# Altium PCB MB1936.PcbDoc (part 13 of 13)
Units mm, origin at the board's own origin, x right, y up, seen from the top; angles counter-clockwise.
Board outline 172 x 137 mm, 6 copper layers (Top Layer, Signal Layer 1, Signal Layer 2, Signal Layer 3, Signal Layer 4, Bottom Layer), stack 1.549 mm thick; 859 components, 672 nets, 3477 pads, 2222 vias.
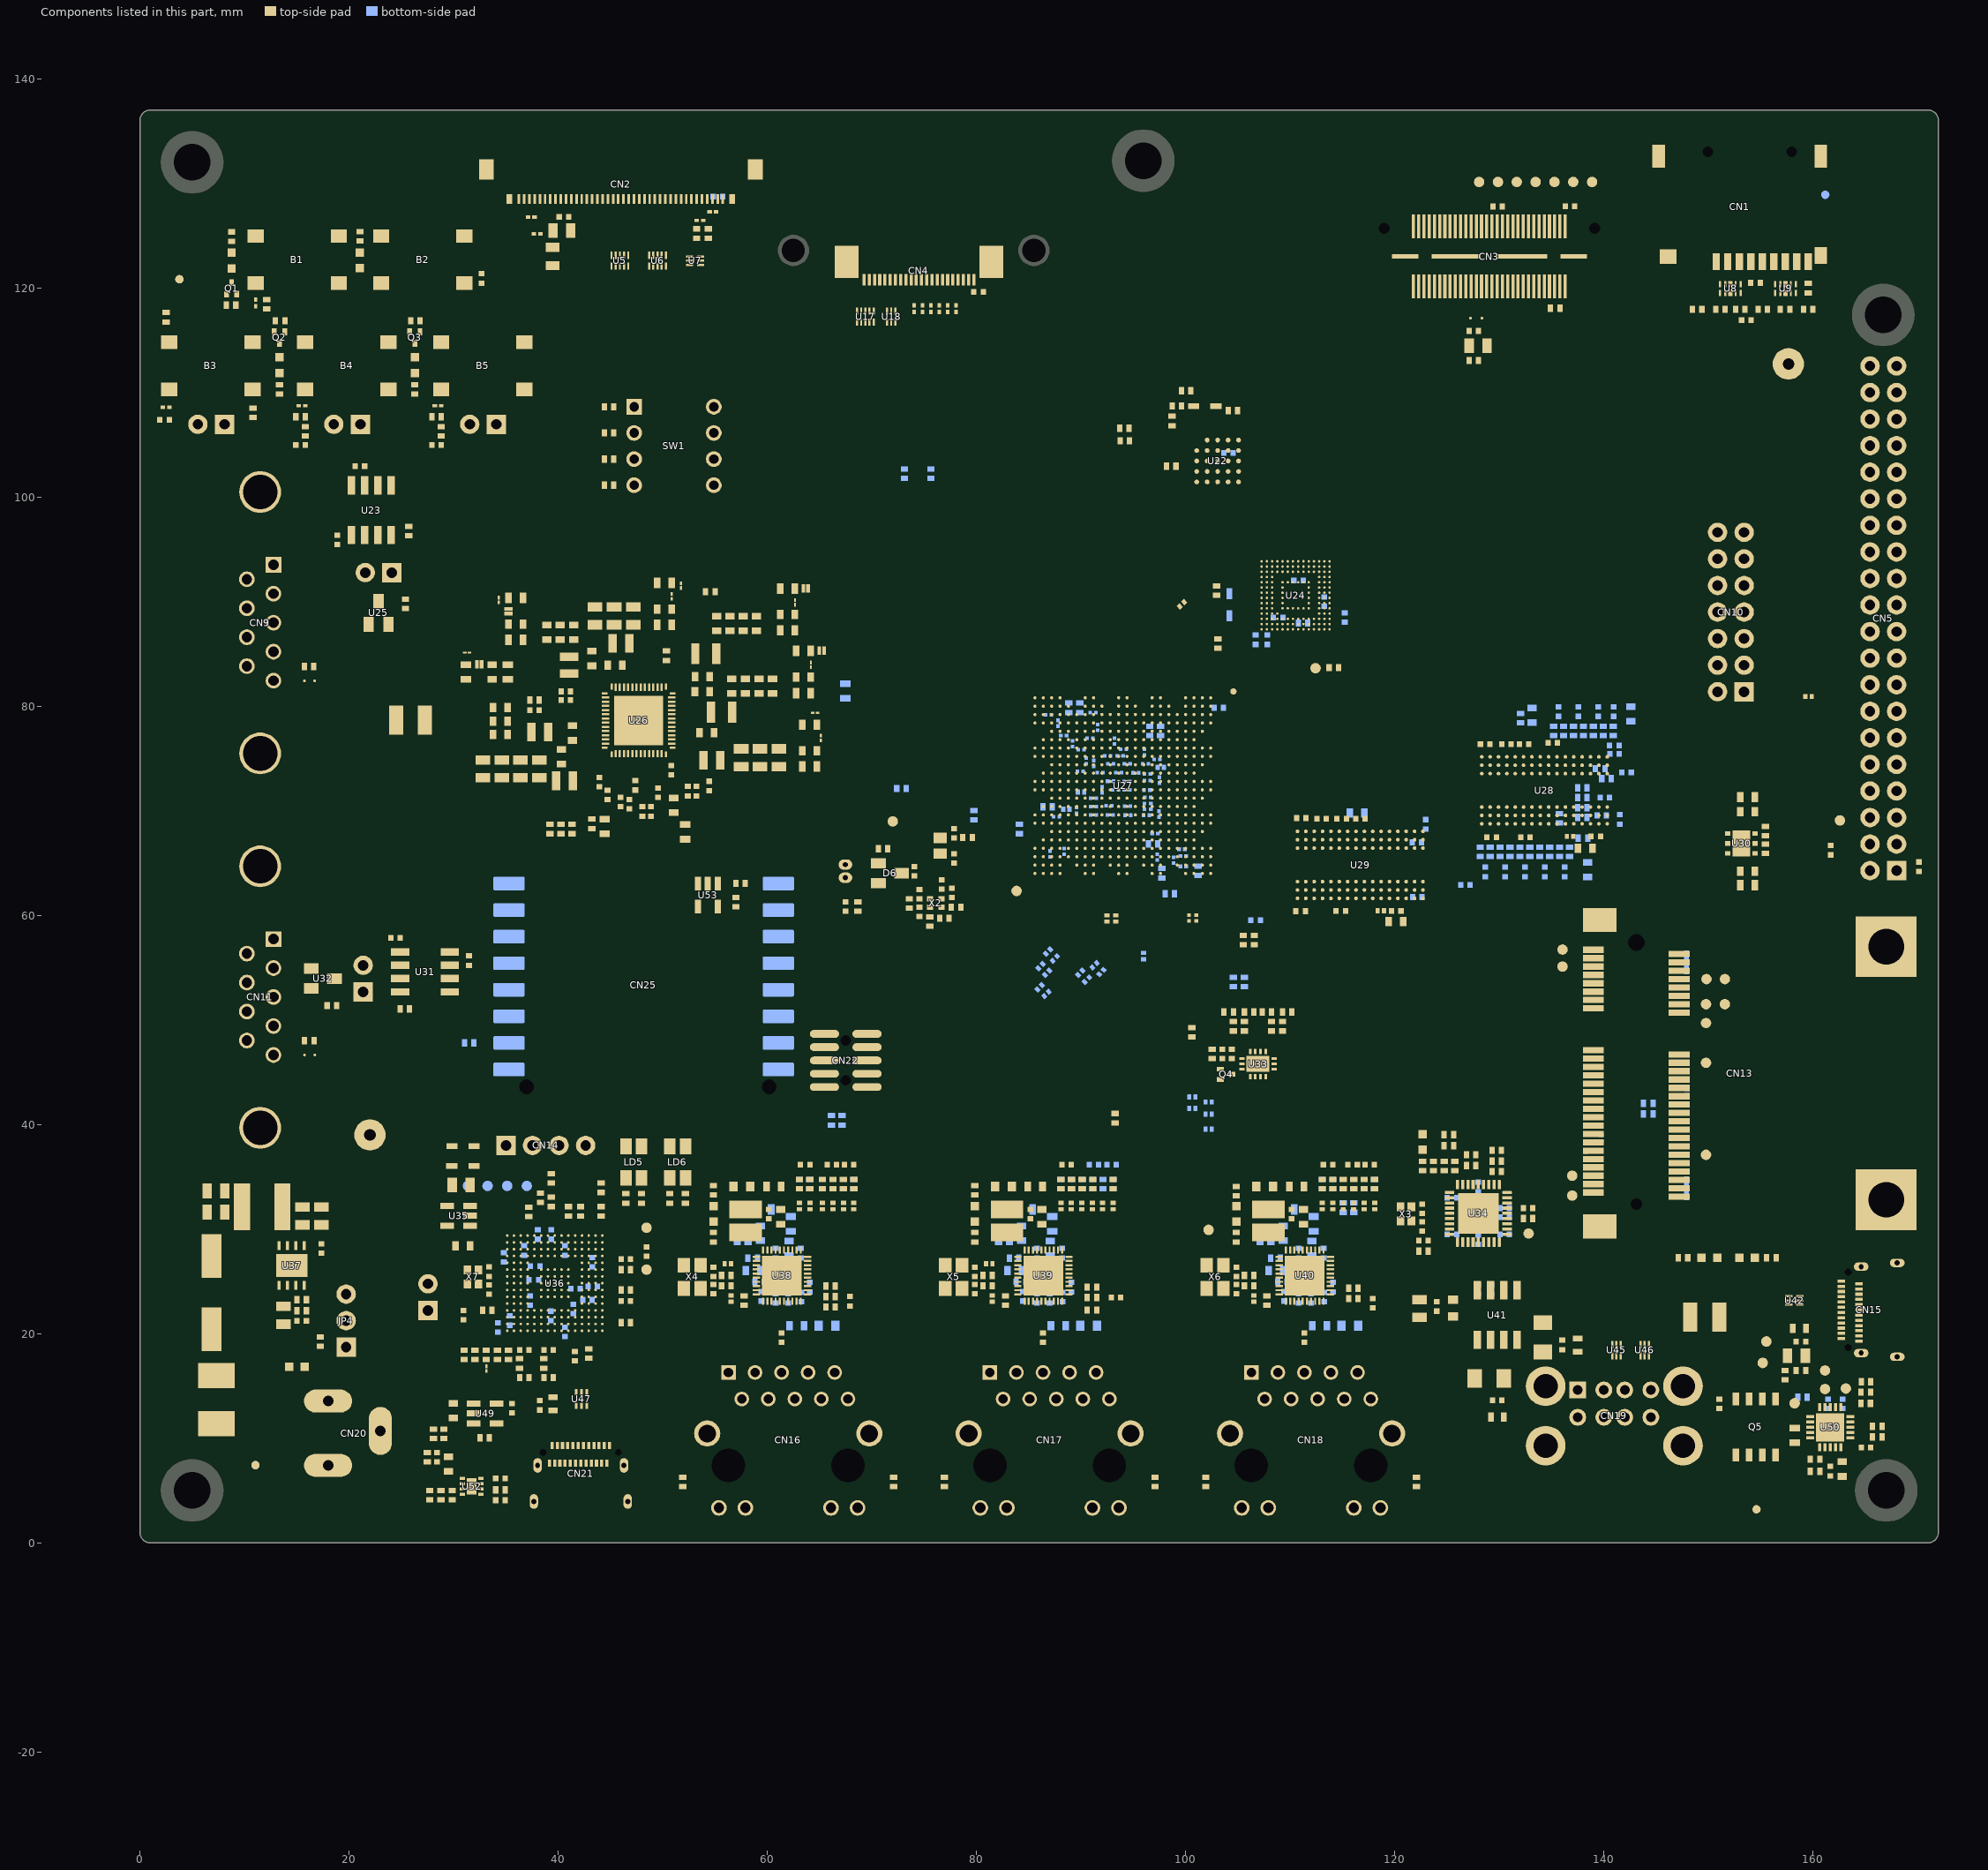
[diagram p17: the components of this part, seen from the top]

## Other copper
Top Layer:
  region net I_SENS_VDDGPU_N: 64.475,84 63.835,84 63.835,82.673 64.475,82.673
  rectangle net VDDGPU: 63.835,83.975 64.475,85.277
  region net I_SENS_VDDCORE_N: 62.95,89.95 62.31,89.95 62.31,88.973 62.95,88.973
  rectangle net VDDCORE: 62.31,89.924 62.95,90.875
  rectangle net VDDGPU: 64.4,84.9 64.95,85.7
  rectangle net VDDCORE: 62.875,90.875 63.425,91.675
  rectangle net 5V_VIN: 38.5,120.925 40.45,122.55
  rectangle net 5V_VIN: 121.675,22.8 123.075,25.2
  rectangle net 5V_VIN: 150.765,7.775 154.32,12.225
  region net NetL2_1: 51.225,80.352 51.55,80.352 52.025,80.827 52.025,83.102 52.027,83.135 52.036,83.166 52.049,83.197 52.064,83.226 52.083,83.254 52.103,83.279 52.127,83.303 52.151,83.323 52.18,83.342 52.208,83.357 52.239,83.37 52.27,83.38 52.303,83.386 52.337,83.389 52.475,83.527 52.475,83.577 52.475,83.651 cw(c52.85,83.651) 52.85,84.026 52.85,86.027 51.62,86.027 ccw(c51.8,85.727) 51.45,85.727 51.45,82.152 51.47,82.149 51.597,82.096 51.709,81.984 51.77,81.837 51.77,81.677 51.725,81.569 51.725,81.018 51.705,80.921 51.65,80.838 51.47,80.658 51.314,80.502 51.225,80.502
  region net NetL1_1: 46.772,84.702 ccw(c46.469,84.71) 46.678,84.929 46.655,84.952 46.655,85.014 46.726,85.021 46.875,84.902
  region net GND: 51.425,78.827 51.35,78.752 51.272,78.752 cw(c51.272,78.625) 51.362,78.715 51.388,78.689 ccw(c51.478,78.779) 51.478,78.652 52.147,78.652 cw(c52.147,78.525) 52.237,78.615 52.3,78.552 52.429,78.681 cw(c52.48,78.63) 52.48,78.702
  region net 5V_VIN: 53.525,82.152 53.525,83.227 52.352,83.227 ccw(c52.352,83.055) 52.18,83.054 52.18,80.646 51.706,80.172 51.47,80.172 51.47,79.907 52.076,79.907 52.547,80.378 52.549,80.365 52.55,80.366 52.55,81.486 52.539,81.497 52.496,81.563 52.465,81.635 52.45,81.713 52.45,81.827 cw(c52.813,81.789) 52.775,82.152
  region net 5V_VIN: 44.43,83.351 44.331,83.252 43.975,83.252 cw(c43.975,83.602) 43.625,83.602 43.625,83.652 42.9,83.652 ccw(c42.9,83.577) 42.825,83.577 42.825,83.227 ccw(c43.027,83.224) 43.025,83.022 45.65,83.022 46.05,82.627 46.312,82.627 45.591,83.348 45.325,83.352
  region net GND: 44.1,82.512 44.007,82.512 ccw(c44.007,82.411) 43.935,82.482 43.655,82.202 ccw(c43.727,82.13) 43.625,82.13 43.625,81.802 44.125,81.802 cw(c44.523,81.809) 44.515,82.207 44.775,82.202 ccw(c44.775,82.25) 44.809,82.216 44.905,82.312
  pour cut-out: 29.525,11.23 29.525,9.62 29.505,9.6 29.1,9.6 28.805,9.305 28.805,7.521 27.074,7.521 26.975,7.62 26.975,8.975 27.62,9.62 27.62,11.23
  region net NetL4_1: 53.725,80.427 53.725,78.427 54.634,78.427 54.634,80.427
  region net NetL3_1: 41.775,81.802 40.588,82.989 41.688,82.989 41.775,82.902 45.38,82.902 45.62,82.662 43.99,82.662 43.968,82.66 43.948,82.656 43.92,82.647 43.901,82.64 43.875,82.626 43.858,82.615 43.835,82.596 43.541,82.301 43.522,82.279 43.511,82.262 43.502,82.246 43.49,82.217 43.486,82.205 43.481,82.189 43.477,82.169 43.476,82.154 43.474,82.14 43.474,81.802
  region net NetL3_1: 42.983,82.872 42.954,82.875 42.925,82.884 42.851,82.916 42.825,82.93 42.803,82.949 42.747,83.007 42.728,83.03 42.714,83.056 42.688,83.121 42.681,83.143 42.658,83.174 42.633,83.194 42.597,83.218 42.551,83.227 41.775,83.227 41.775,82.09
  region net NetL7_1: 42.075,73.177 41.775,72.877 41,72.877 41,73.777 42.075,74.847
  region net NetL1_1: 47.195,85.102 46.85,84.757 46.395,85.212 46.395,86.902 47.195,86.902
  region net NetL5_1: 38.625,78.775 38.85,79 40.225,79 40.225,77.15 39.702,76.627 39.425,76.627 38.625,76.627
  region net I_SENS_1V8_N: 50.535,90.475 50.535,89.277 51.175,89.277 51.175,90.475
  region net I_SENS_VDDIO_N: 65.025,76.975 64.435,76.385 64.435,76.172 65.075,76.172 65.803,76.9 65.902,76.9 65.827,76.975
  region net VDDIO: 65.827,76.975 65.902,76.9 66,76.9 66.125,77.025 65.047,78.103 64.775,78.103 64.775,78.067 64.441,77.733 65.025,77.15 65.025,76.975
  region net VDDCPU: 36.44,92.248 36.715,92.248 36.84,92.123 36.84,91.123 36.722,91.005 35.692,91.005 35.565,90.878 35.565,90.83 34.945,90.83 34.77,91.005 34.77,92.078 34.94,92.248
  region net GND: 50.3,70.052 50.395,70.147 50.7,70.147 50.7,69.507 50.345,69.507 50.3,69.552 50.05,69.552 50.05,70.052
  region net VDDGPU: 63.68,86.92 63.935,87.175 65.7,87.175 65.85,87.025 65.85,86.075 65.695,85.92 64.59,85.92 64.475,85.805 64.475,85.757 63.855,85.757 63.68,85.932
  region net VDDCORE: 63.825,93.15 64.1,93.15 64.225,93.025 64.225,92.025 64.05,91.85 63.02,91.85 62.95,91.78 62.95,91.732 62.33,91.732 62.155,91.907 62.155,92.98 62.325,93.15
  region net GND: 32.825,75.625 32.675,75.475 32.675,75.225 33.5,75.225 33.5,75.7 33.325,75.875 32.825,75.875
  region net GND: 32.825,75.625 32.975,75.475 32.975,75.225 32.1,75.225 32.1,75.65 32.325,75.875 32.825,75.875
  region net GND: 34.625,75.625 34.475,75.475 34.475,75.225 35.3,75.225 35.3,75.7 35.125,75.875 34.625,75.875
  region net GND: 34.625,75.625 34.775,75.475 34.775,75.225 33.9,75.225 33.9,75.65 34.125,75.875 34.625,75.875
  region net GND: 36.425,75.625 36.275,75.475 36.275,75.225 37.1,75.225 37.1,75.7 36.925,75.875 36.425,75.875
  region net GND: 36.425,75.625 36.575,75.475 36.575,75.225 35.7,75.225 35.7,75.65 35.925,75.875 36.425,75.875
  region net GND: 38.225,75.625 38.075,75.475 38.075,75.225 38.9,75.225 38.9,75.7 38.725,75.875 38.225,75.875
  region net GND: 38.225,75.625 38.375,75.475 38.375,75.225 37.5,75.225 37.5,75.65 37.725,75.875 38.225,75.875
  region net VDD_DDR: 30.675,84.297 30.559,84.297 30.206,84.65 29.075,84.65 29.075,84.297 29.075,83.657 29.075,83.3 30.271,83.3 30.628,83.657 31.052,83.657 31.052,84.297
  region net 1V8: 51.175,93.025 51.625,93.025 51.75,92.9 51.75,92.5 51.65,92.4 51.25,92.4 51.175,92.325 51.175,90.475 50.535,90.475 50.535,92.44 50.4,92.575 50.4,92.9 50.525,93.025 50.7,93.025
  region net GND: 41.125,75.779 40.93,75.974 40.93,76.429 41.82,76.429 41.82,75.974 41.625,75.779
  region net GND: 39.15,88.7 39.345,88.505 39.345,88.05 38.455,88.05 38.455,88.505 38.65,88.7
  region net GND: 40.45,88.7 40.645,88.505 40.645,88.05 39.755,88.05 39.755,88.505 39.95,88.7
  region net GND: 41.75,88.7 41.945,88.505 41.945,88.05 41.055,88.05 41.055,88.505 41.25,88.7
  region net GND: 61.08,76.702 61.23,76.552 61.23,76.302 60.4,76.302 60.4,76.772 60.58,76.952 61.08,76.952
  region net GND: 61.08,76.702 60.93,76.552 60.93,76.302 61.8,76.302 61.8,76.732 61.58,76.952 61.08,76.952
  region net GND: 59.28,76.702 59.43,76.552 59.43,76.302 58.6,76.302 58.6,76.772 58.78,76.952 59.28,76.952
  region net GND: 59.28,76.702 59.13,76.552 59.13,76.302 60,76.302 60,76.732 59.78,76.952 59.28,76.952
  region net GND: 57.48,76.702 57.33,76.552 57.33,76.302 58.2,76.302 58.2,76.732 57.98,76.952 57.48,76.952
  region net 5V_VIN: 40.625,78.352 40.72,78.447 41.364,78.447 41.364,77.807 40.375,77.807 40.375,78.352
  region net GND: 47.225,90.252 47.375,90.102 47.375,89.852 46.5,89.852 46.5,90.277 46.725,90.502 47.225,90.502
  region net GND: 47.225,90.252 47.075,90.102 47.075,89.852 47.9,89.852 47.9,90.327 47.725,90.502 47.225,90.502
  region net GND: 45.375,90.252 45.525,90.102 45.525,89.852 44.65,89.852 44.65,90.277 44.875,90.502 45.375,90.502
  region net GND: 45.375,90.252 45.225,90.102 45.225,89.852 46.05,89.852 46.05,90.327 45.875,90.502 45.375,90.502
  region net GND: 60.75,83.652 60.945,83.457 60.945,82.602 60.055,82.602 60.055,83.457 60.25,83.652
  region net GND: 59.45,83.652 59.645,83.457 59.645,82.602 58.755,82.602 58.755,83.457 58.95,83.652
  region net GND: 58.15,83.652 58.345,83.457 58.345,82.602 57.455,82.602 57.455,83.457 57.65,83.652
  region net GND: 56.85,83.652 57.045,83.457 57.045,82.602 56.155,82.602 56.155,83.457 56.35,83.652
  region net GND: 55.5,81.152 55.305,80.957 54.45,80.957 54.45,81.847 55.305,81.847 55.5,81.652
  region net GND: 55.525,82.577 55.33,82.382 54.475,82.382 54.475,83.272 55.33,83.272 55.525,83.077
  region net GND: 55.4,89.627 55.595,89.432 55.595,88.577 54.705,88.577 54.705,89.432 54.9,89.627
  region net GND: 56.675,89.627 56.87,89.432 56.87,88.577 55.98,88.577 55.98,89.432 56.175,89.627
  region net GND: 57.95,89.627 58.145,89.432 58.145,88.577 57.255,88.577 57.255,89.432 57.45,89.627
  region net GND: 59.225,89.627 59.42,89.432 59.42,88.577 58.53,88.577 58.53,89.432 58.725,89.627
  region net GND: 55.702,77.202 55.507,77.007 55.2,77.007 55.2,77.897 55.675,77.897 55.87,77.702 55.87,77.202
  region net GND: 32.8,80.127 32.995,80.322 33.775,80.322 33.775,79.432 32.995,79.432 32.8,79.627
  region net GND: 32.8,78.827 32.995,79.022 33.775,79.022 33.775,78.132 32.995,78.132 32.8,78.327
  region net 5V_VIN: 53.325,80.077 52.75,79.502 52.075,79.502 52.075,79.677 52.6,80.202
  region net GND: 39.3,75.577 39.345,75.532 39.905,75.532 39.95,75.577 39.95,76.172 39.645,76.172 39.55,76.077 39.3,76.077
  region net 5V_VIN: 39.3,74.775 39.95,74.775 39.95,74.132 39.645,74.132 39.55,74.227 39.3,74.227
  region net GND: 32.8,77.527 32.995,77.722 33.775,77.722 33.775,76.832 32.995,76.832 32.8,77.027
  region net GND: 43.8,84.15 43.997,84.347 44.45,84.347 44.45,83.457 43.993,83.457 43.8,83.65
  region net GND: 52.03,78.952 52.48,78.952 52.48,78.652 52.355,78.527 52.18,78.702 52.03,78.702
  region net 5V_VIN: 53.35,81.752 53.395,81.707 53.395,81.352 52.755,81.352 52.755,81.657 52.85,81.752 52.85,82.002 53.35,82.002
  region net 5V_VIN: 53.275,76.702 53.125,76.852 53.125,77.102 53.82,77.102 53.82,76.747 53.775,76.702 53.775,76.452 53.275,76.452
  region net GND: 57.48,76.702 57.63,76.552 57.63,76.302 56.8,76.302 56.8,76.772 56.98,76.952 57.48,76.952
  region net 5V_VIN: 53.275,76.702 53.275,76.952 52.375,77.852 53.125,77.852 53.447,77.53
  region net 5V_VIN: 53.395,81.002 53.395,80.147 53.325,80.077 53.2,80.202 52.6,80.202 52.755,80.357 52.755,81.002
  region net 5V_VIN: 46.375,84.652 46.47,84.557 46.47,84.252 45.83,84.252 45.83,84.607 45.875,84.652 45.875,84.902 46.375,84.902
  pour cut-out: 63.18,74.752 56.83,74.752 56.83,75.402 63.18,75.402
  pour cut-out: 32.1,73.6 38.75,73.6 38.75,74.4 32.1,74.4
  region net 5V_VIN: 53.375,83.577 53.525,83.427 53.525,83.177 52.725,83.177 52.725,83.427 52.875,83.577 52.875,83.827 53.375,83.827
  region net GND: 43.475,86.2 43.67,86.005 43.67,85.55 42.78,85.55 42.78,86.005 42.975,86.2
  region net 5V_VIN: 42.475,84.127 42.52,84.172 42.875,84.172 42.875,83.477 42.625,83.477 42.475,83.627 42.225,83.627 42.225,84.127
  region net GND: 51.121,81.483 51.22,81.483 51.249,81.48 51.278,81.471 51.304,81.457 51.327,81.439 51.345,81.416 51.37,81.382 51.37,81.057 51.47,81.057 51.47,81.757 51.121,81.757
  region net 5V_VIN: 46.625,82.552 46.6,82.552 45.83,83.322 45.83,83.652 46.47,83.652 46.47,83.432 46.6,83.302 46.6,82.752
  region net GND: 44.775,82.202 44.44,82.202 44.44,82.212
  region net GND: 43.525,90.252 43.375,90.102 43.375,89.852 44.2,89.852 44.2,90.327 44.025,90.502 43.525,90.502
  region net GND: 43.525,90.252 43.675,90.102 43.675,89.852 42.8,89.852 42.8,90.277 43.025,90.502 43.525,90.502
  pour cut-out: 55.1,75.902 54.3,75.902 54.3,73.802 55.1,73.802
  pour cut-out: 56.155,80.277 55.095,80.277 55.095,78.177 56.155,78.177
  pour cut-out: 54.645,86.077 53.585,86.077 53.585,83.977 54.645,83.977
  pour cut-out: 41.14,73.927 40.08,73.927 40.08,71.827 41.14,71.827
  pour cut-out: 46.355,87.052 45.635,87.052 45.635,84.952 46.355,84.952
  pour cut-out: 40,84.432 40,83.372 42.1,83.372 42.1,84.432
  pour cut-out: 40.7,75.427 38.75,75.427 38.75,74.852 40.7,74.852
  region net 5V_VIN: 42.075,75.727 41.916,75.727 41.889,75.701 41.848,75.669 41.802,75.642 41.754,75.622 41.703,75.609 41.651,75.602 41.625,75.601 41.125,75.601 41.099,75.602 41.047,75.609 40.996,75.622 40.948,75.642 40.902,75.669 40.861,75.701 40.85,75.277 40.85,74.772 40.575,74.772 40.575,74.132 41.03,74.132 41.799,74.901 41.799,75.011 41.803,75.054 41.813,75.097 41.829,75.137 41.852,75.173 41.88,75.206 42.238,75.564
  pour cut-out: 37.695,76.477 38.755,76.477 38.755,78.577 37.695,78.577
  pour cut-out: 55.055,75.702 56.83,75.702 56.83,74.427 55.5,74.427
  pour cut-out: 73.075,61.98 77.094,61.98 77.098,61.976 77.374,61.976 77.65,61.7 77.65,60.35 76.77,59.47 73.69,59.47 73.075,60.085
  pour cut-out: 75.75,68.05 75.75,65.25 78.28,65.25 78.28,68.05
  pour cut-out: 12.583,29.813 10.7,29.813 10.7,34.525 10.988,34.525 11.038,34.575 11.038,30.133 11.31,29.86 12.535,29.86
  pour cut-out: 13.025,28.975 13.025,27.6 16.025,27.6 16.025,27.825 13.745,27.825 13.725,27.845 13.725,28.575 13.325,28.975 13.29,28.975
  pour cut-out: 13.025,25.175 13.025,25.4 16.025,25.4 16.025,23.825 15.925,23.725 13.181,23.725 13.019,23.887
  pour cut-out: 34.725,29.25 34.725,29.775 44.65,29.775 44.65,19.85 34.725,19.85
  pour cut-out: 106.875,94 107.125,94.25 114,94.25 114.175,94.075 114.175,87.1 114,86.925 107.15,86.925 106.875,87.2
  pour cut-out: 105.474,100.794 105.7,101.02 105.7,105.75 105.45,106 100.7,106 100.375,105.675 100.375,101.05 100.616,100.809
  pour cut-out: 105.294,61.106 107.785,61.106 109.726,59.165 116.307,59.165 117.465,60.323 123.465,60.323 125.578,62.435 125.578,65.203 126.003,65.628 134.069,65.628 136.445,68.004 141.215,68.004 143.2,69.989 143.2,70.147 143.205,70.152 143.205,76.09 138.963,80.333 104.025,80.333 104.025,81.125 103.65,81.5 85,81.5 85,63.4 103,63.4
  text "1" at 134.025,133.811 h2
Signal Layer 1:
  text "2" at 135.309,133.811 h2
Signal Layer 2:
  text "3" at 136.817,133.822 h2
Signal Layer 3:
  text "4" at 139.181,133.814 h2
Signal Layer 4:
  text "5" at 140.661,133.833 h2
Bottom Layer:
  pour cut-out: 89.032,64.582 90.15,65.7 90.325,65.7 90.325,59.611 90.175,59.461 89.689,59.461 89.032,60.118
  pour cut-out: 126.357,79.378 131.948,79.378 132.025,79.3 132.025,69.1 131.125,68.2 129.69,68.2 127.571,66.075 127.571,64.967 126.147,63.544 126.147,61.831 122.294,57.978 113.123,57.978 110.435,60.666 109.939,60.666 109.448,60.175 105.551,60.175 102.4,63.326 102.4,63.45 99.925,65.925 99.925,66.325 97.5,68.75 97.5,75.901 99.265,77.665 107.979,77.665 114.492,71.151 118.131,71.151
  text "6" at 142.16,133.822 h2

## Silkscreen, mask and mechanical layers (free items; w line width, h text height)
Top Overlay:
  lines w0.12: 155.375,20.45 155.375,23.475 ; 155.375,21.325 156.775,19.925 156.4,19.925 ; 156.775,19.95 156.775,20.375
  text "LVDS" at 43.824,132.909 h2
  text "DSI" at 118.358,128.059 h2
  text "CSI" at 73.083,126.709 h2
  text "RESET" at 12.559,126.134 h2
  text "WAKE UP" at 22.75,126.12 h2
  text "SDcard" at 162.691,124.846 h2 r90
  text "E" at 106.861,124.764 h12
  text "I" at 97.6,117.481 h15
  text "USER1" at 30.17,116.009 h2
  text "TAMPER" at 3.223,115.884 h2
  text "USER2" at 17.153,115.859 h2
  text "G" at 88.2,115.673 h11
  text "H" at 106.15,114.422 h15
  text "C" at 111.265,108.269 h11
  text "0" at 56.482,108.018 h2
  text "1" at 56.664,105.507 h2
  text "2" at 56.473,103.007 h2
  text "3" at 56.481,100.518 h2
  text "BOOT" at 48.747,97.159 h2
  text "1V8" at 155.384,96.151 h1.5
  text "DDR" at 155.405,93.6 h1.5
  text "GPU" at 155.432,91.06 h1.5
  text "GND" at 155.376,88.52 h1.5
  text "FDCAN1" at 16.891,88.257 h2 r90
  text "CORE" at 155.353,85.965 h1.5
  text "CPU" at 155.467,83.44 h1.5
  text "VDDIO" at 155.335,81.395 h1.5
  text "GPIO" at 163.166,79.148 h2 r90
  text "PWR meas" at 147.845,77.265 h2
  text "VBAT" at 65.16,66.609 h2
  text "FDCAN2" at 17.416,57.814 h2 r90
  text "J" at 44.05,49.342 h15
  text "MB1936D" at 42.375,45.327 h3
  text "miniPCIe" at 158.514,44.809 h2
  text "MIPI10" at 64.797,41.288 h2
  text "RESERVED" at 34.018,39.884 h2
  text "USB_DRD" at 162.165,28.126 h2
  text "ETH1" at 97.918,12.947 h2 r90
  text "ETH2" at 72.918,12.829 h2 r90
  text "ETH3" at 122.907,12.822 h2 r90
  text "STLINK" at 50.416,3.608 h2 r90
  text "USB" at 150.266,1.827 h2 r90
  text "USB_PWR" at 48.474,1.706 h2 r90
  text "5V_3A" at 12.316,0.922 h2 r90
Bottom Overlay:
  lines w0.15: 97.85,68.8 97.85,69.025 ; 98.075,69.025 97.85,69.025 ; 99.3,65.2 100.525,65.2 101.125,65.8 101.725,65.8 ; 113.55,66 113.55,65.4 113.25,65.1 109.1,65.1 106.375,67.825 102.2,67.825 101.325,68.7 98.175,68.7 97.85,69.025
  lines w0.2: 113.225,65.7 113.55,66.025 113.875,65.7
  text "AN" at 64.754,62.645 h1.5
  text "PWM" at 33.25,62.52 h1.5
  text "RST" at 65.589,60.128 h1.5
  text "INT" at 33.237,60.003 h1.5
  text "RX" at 33.237,57.503 h1.5
  text "CS" at 64.765,57.503 h1.5
  text "SCK" at 65.733,55.003 h1.5
  text "TX" at 33.237,54.878 h1.5
  text "SCL" at 33.237,52.378 h1.5
  text "MISO" at 66.309,52.378 h1.5
  text "SDA" at 33.237,49.878 h1.5
  text "MOSI" at 66.248,49.878 h1.5
  text "+3V3" at 66.076,47.634 h1.5
  text "+5V" at 33.237,46.261 h1.5
  text "GND" at 65.877,45.003 h1.5
  text "GND" at 33.237,44.753 h1.5
Top Solder:
  region: 133.736,135.455 133.736,133.455 142.486,133.455 142.486,135.455
Bottom Solder:
  region: 133.736,135.455 133.736,133.455 142.486,133.455 142.486,135.455
M1-Board Shape:
  lines w0.1: 1,137 ccw(c1,136) 0,136 0,95 0,1 ccw(c1,1) 1,0 171,0 ccw(c171,1) 172,1 172,136 ccw(c171,136) 171,137 ; 1,137 1,137 ; 1,137 171,137 ; 171,137 171,137
M2-Board Dimensions:
  lines w0.1: 1,137 ccw(c1,136) 0,136 0,1 ccw(c1,1) 1,0 171,0 ccw(c171,1) 172,1 172,136 ccw(c171,136) 171,137 ; 1,137 1,137 ; 1,137 171,137 ; 171,137 171,137
M3-Top Dimensions:
  circle w0.1: c85.5,123.578 r1.1
  circle w0.1: c5,132 r1.75
Drill Drawing:
  drawing of 373 lines, arcs and shapes, not listed
  text "PCB SPECIFICATIONS :" at 3.455,183.85 h3
  text "MINIMUN PARAMETERS" at 155.325,183.145 h3
  text "PCB : TYPE 3" at 194.663,183.121 h3
  text "Layer" at 244.479,182.451 h2
  text "Name" at 252.848,182.45 h2
  text "Material" at 269.029,182.45 h2
  text "Thickness" at 283.573,182.45 h2
  text "Constant" at 295.517,182.451 h2
  text "A.   MATERIAL :" at 3.455,179.85 h3
  text "FR-4" at 41.955,179.85 h3
  text "TG-170" at 58.455,179.85 h3
  text "X  TG-150" at 76.705,179.85 h3
  text "TG-140" at 92.705,179.85 h3
  text "Top Overlay" at 252.848,178.451 h2
  text "DEFAULT" at 155.325,177.645 h3
  text "ASPECT-RATIO, AXE Z :" at 194.663,177.621 h3
  text "B.   MATERIAL FAMILY :" at 3.455,176.85 h3
  text "N/A" at 41.955,176.85 h3
  text "Top Solder" at 252.848,174.451 h2
  text "Solder Resist" at 269.029,174.451 h2
  text "0,025mm" at 283.573,174.45 h2
  text "3.5" at 295.517,174.451 h2
  text "C.   SOLDERMASK COLOR :" at 3.455,173.85 h3
  text "GREEN" at 41.955,173.85 h3
  text "X  BLUE" at 58.455,173.85 h3
  text "RED" at 76.705,173.85 h3
  text "BLACK" at 92.705,173.85 h3
  text "TRACKS : 0.100mm           / GAPS : 0.100mm" at 155.325,171.895 h3
  text "6 :1  to  8 :1 / LEVEL \"B\"" at 194.682,170.874 h3
  text "D.   SILKSCREEN COLOR :" at 3.455,170.85 h3
  text "X  WHITE" at 41.955,170.85 h3
  text "YELLOW" at 58.455,170.85 h3
  text "BLACK" at 76.705,170.85 h3
  text "1" at 244.479,170.45 h2
  text "Top Layer" at 252.848,170.451 h2
  text "0,037mm" at 283.573,170.45 h2
  text "E.   SURFACE FINISH :" at 3.455,167.85 h3
  text "X  ENIG" at 41.955,167.85 h3
  text "IMMERSION SILVER" at 58.455,167.85 h3
  text "IMMERSION TIN" at 92.705,167.85 h3
  text "BGA :" at 155.3,167.07 h3
  text "Dielectric 1" at 252.848,166.45 h2
  text "0,072mm" at 283.573,166.45 h2
  text "3.8" at 295.517,166.451 h2
  text "HASL" at 41.955,164.85 h3
  text "HASL (PB-FREE)" at 58.455,164.85 h3
  text "GOLDEN FINGER" at 92.705,164.85 h3
  text "2" at 244.478,162.45 h2
  text "Signal Layer 1" at 252.848,162.451 h2
  text "0,035mm" at 283.573,162.45 h2
  text "F.   IMPEDANCE CONTROL :" at 3.455,161.85 h3
  text "NO" at 41.955,161.85 h3
  text "X  YES" at 58.455,161.85 h3
  text "TRACKS : 0.090mm           / GAPS : 0.090mm" at 155.3,161.32 h3
  text "G.   THROUGH VIA :" at 3.455,158.85 h3
  text "PLUG THE VIAS WHICH ARE COVERED WITH SOLDERMASK ONE OR TWO SIDE." at 41.955,158.85 h3
  text "Dielectric 2" at 252.848,158.45 h2
  text "0,500mm" at 283.573,158.45 h2
  text "5" at 295.517,158.451 h2
  text "PLUG MATERIAL :" at 41.955,155.85 h3
  text "X  SOLDERMASK" at 67.455,155.85 h3
  text "NON-CONDUCTIVE EPOXY." at 92.705,155.85 h3
  text "3" at 244.479,154.451 h2
  text "Signal Layer 2" at 252.848,154.451 h2
  text "0,035mm" at 283.573,154.45 h2
  text "H.   STACK-UP :" at 3.455,152.85 h3
  text "SEE LAYER STACK-UP SEQUENCE FOR OVERALL THICKNESS." at 41.955,152.85 h3
  text "Dielectric 3" at 252.848,150.451 h2
  text "0,191mm" at 283.573,150.45 h2
  text "4.3" at 295.517,150.451 h2
  text "4" at 244.479,146.45 h2
  text "Signal Layer 3" at 252.848,146.451 h2
  text "0,035mm" at 283.573,146.45 h2
  text "Dielectric 4" at 252.848,142.45 h2
  text "0,500mm" at 283.573,142.45 h2
  text "5" at 295.517,142.451 h2
  text "5" at 244.479,138.451 h2
  text "Signal Layer 4" at 252.848,138.451 h2
  text "0,035mm" at 283.573,138.45 h2
  text "Dielectric 5" at 252.848,134.451 h2
  text "0,072mm" at 283.573,134.45 h2
  text "3.8" at 295.517,134.451 h2
  text "6" at 244.479,130.451 h2
  text "Bottom Layer" at 252.848,130.451 h2
  text "0,037mm" at 283.573,130.45 h2
  text "Bottom Solder" at 252.848,126.451 h2
  text "Solder Resist" at 269.029,126.451 h2
  text "0,025mm" at 283.573,126.45 h2
  text "3.5" at 295.517,126.451 h2
  text "Bottom Overlay" at 252.848,122.451 h2
  text "Symbol" at 197.789,108.783 h2.4
  text "Count" at 207.181,108.783 h2.4
  text "Hole Size" at 217.94,108.783 h2.4
  text "Plated" at 237.19,108.783 h2.4
  text "Hole Type" at 245.438,108.783 h2.4
  text "Drill Layer Pair" at 257.441,108.783 h2.4
  text "Via/Pad" at 280.192,108.783 h2.4
  text "Pad Shape" at 290.029,108.783 h2.4
  text "Hole Length" at 302.876,108.783 h2.4
  text "416" at 207.181,104.642 h2
  text "0.200mm (7.87mil)" at 217.94,104.643 h2
  text "PTH" at 237.19,104.642 h2
  text "Round" at 245.438,104.642 h2
  text "Top Layer - Bottom Layer" at 257.441,104.643 h2
  text "Via" at 280.192,104.642 h2
  text "Rounded" at 290.029,104.642 h2
  text "-" at 302.876,104.641 h2
  text "D" at 197.001,104.388 h1.84
  text "145" at 207.181,100.502 h2
  text "0.250mm (9.84mil)" at 217.94,100.502 h2
  text "PTH" at 237.19,100.501 h2
  text "Round" at 245.438,100.502 h2
  text "Top Layer - Bottom Layer" at 257.441,100.502 h2
  text "Via" at 280.192,100.502 h2
  text "Rounded" at 290.029,100.502 h2
  text "-" at 302.876,100.501 h2
  text "E" at 197.001,100.247 h1.84
  text "1661" at 207.181,96.361 h2
  text "0.350mm (13.78mil)" at 217.94,96.362 h2
  text "PTH" at 237.19,96.361 h2
  text "Round" at 245.438,96.361 h2
  text "Top Layer - Bottom Layer" at 257.441,96.362 h2
  text "Via" at 280.192,96.361 h2
  text "Rounded" at 290.029,96.361 h2
  text "-" at 302.876,96.36 h2
  text "F" at 197.001,96.107 h1.84
  text "2" at 207.181,92.22 h2
  text "0.500mm (19.69mil)" at 217.94,92.221 h2
  text "PTH" at 237.19,92.22 h2
  text "Round" at 245.438,92.22 h2
  text "Top Layer - Bottom Layer" at 257.441,92.221 h2
  text "Pad" at 280.192,92.22 h2
  text "Rounded" at 290.029,92.22 h2
  text "-" at 302.876,92.22 h2
  text "8" at 207.181,88.08 h2
  text "0.500mm (19.69mil)" at 217.94,88.08 h2
  text "PTH" at 237.19,88.079 h2
  text "Slot" at 245.438,88.08 h2
  text "Top Layer - Bottom Layer" at 257.441,88.08 h2
  text "Pad" at 280.192,88.08 h2
  text "Rounded" at 290.029,88.08 h2
  text "1.100mm (43.31mil)" at 302.876,88.08 h2
  text "H" at 197.001,87.826 h1.84
  text "2" at 207.181,83.939 h2
  text "0.650mm (25.59mil)" at 217.94,83.94 h2
  text "NPTH" at 237.19,83.939 h2
  text "Round" at 245.438,83.939 h2
  text "Top Layer - Bottom Layer" at 257.441,83.94 h2
  text "Pad" at 280.192,83.939 h2
  text "Rounded" at 290.029,83.939 h2
  text "-" at 302.876,83.938 h2
  text "B" at 197.001,83.685 h1.84
  text "2" at 207.181,79.798 h2
  text "0.650mm (25.59mil)" at 217.94,79.799 h2
  text "NPTH" at 237.19,79.798 h2
  text "Slot" at 245.438,79.799 h2
  text "Top Layer - Bottom Layer" at 257.441,79.799 h2
  text "Pad" at 280.192,79.798 h2
  text "Rounded" at 290.029,79.798 h2
  text "0.950mm (37.40mil)" at 302.876,79.799 h2
  text "I" at 197.307,79.544 h1.84
  text "38" at 207.181,75.658 h2
  text "0.900mm (35.43mil)" at 217.94,75.659 h2
  text "PTH" at 237.19,75.657 h2
  text "Round" at 245.438,75.658 h2
  text "Top Layer - Bottom Layer" at 257.441,75.658 h2
  text "Pad" at 280.192,75.658 h2
  text "(Mixed)" at 290.029,75.659 h2
  text "-" at 302.876,75.657 h2
  text "8" at 207.181,71.517 h2
  text "0.920mm (36.22mil)" at 217.94,71.518 h2
  text "PTH" at 237.19,71.517 h2
  text "Round" at 245.438,71.517 h2
  text "Top Layer - Bottom Layer" at 257.441,71.518 h2
  text "Pad" at 280.192,71.517 h2
  text "(Mixed)" at 290.029,71.518 h2
  text "-" at 302.876,71.517 h2
  text "4" at 207.181,67.376 h2
  text "1.000mm (39.37mil)" at 217.94,67.377 h2
  text "NPTH" at 237.19,67.376 h2
  text "Round" at 245.438,67.377 h2
  text "Top Layer - Bottom Layer" at 257.441,67.377 h2
  text "Pad" at 280.192,67.377 h2
  text "Rounded" at 290.029,67.377 h2
  text "-" at 302.876,67.376 h2
  text "103" at 207.181,63.236 h2
  text "1.000mm (39.37mil)" at 217.94,63.237 h2
  text "PTH" at 237.19,63.236 h2
  text "Round" at 245.438,63.236 h2
  text "Top Layer - Bottom Layer" at 257.441,63.237 h2
  text "Pad" at 280.192,63.236 h2
  text "Rounded" at 290.029,63.236 h2
  text "-" at 302.876,63.235 h2
  text "3" at 207.181,59.096 h2
  text "1.000mm (39.37mil)" at 217.94,59.096 h2
  text "PTH" at 237.19,59.095 h2
  text "Slot" at 245.438,59.096 h2
  text "Top Layer - Bottom Layer" at 257.441,59.096 h2
  text "Pad" at 280.192,59.095 h2
  text "Rounded" at 290.029,59.095 h2
  text "3.500mm (137.79mil)" at 302.876,59.096 h2
  text "2" at 207.181,54.954 h2
  text "1.050mm (41.34mil)" at 217.94,54.956 h2
  text "NPTH" at 237.19,54.954 h2
  text "Round" at 245.438,54.955 h2
  text "Top Layer - Bottom Layer" at 257.441,54.955 h2
  text "Pad" at 280.192,54.955 h2
  text "Rounded" at 290.029,54.955 h2
  text "-" at 302.876,54.954 h2
  text "1" at 207.181,50.814 h2
  text "1.100mm (43.31mil)" at 217.94,50.815 h2
  text "NPTH" at 237.19,50.814 h2
  text "Round" at 245.438,50.814 h2
  text "Top Layer - Bottom Layer" at 257.441,50.815 h2
  text "Pad" at 280.192,50.814 h2
  text "Rounded" at 290.029,50.814 h2
  text "-" at 302.876,50.814 h2
  text "2" at 207.181,46.673 h2
  text "1.100mm (43.31mil)" at 217.94,46.674 h2
  text "PTH" at 237.19,46.673 h2
  text "Round" at 245.438,46.674 h2
  text "Top Layer - Bottom Layer" at 257.441,46.674 h2
  text "Pad" at 280.192,46.674 h2
  text "Rounded" at 290.029,46.674 h2
  text "-" at 302.876,46.673 h2
  text "1.400mm (55.12mil)" at 217.94,42.534 h2
  text "Round" at 245.438,42.533 h2
  text "Top Layer - Bottom Layer" at 257.441,42.534 h2
  text "Pad" at 280.192,42.533 h2
  text "Rounded" at 290.029,42.533 h2
  text "2" at 207.181,42.533 h2
  text "NPTH" at 237.19,42.533 h2
  text "-" at 302.876,42.532 h2
  text "A" at 197.001,42.279 h1.84
  text "1.600mm (62.99mil)" at 217.94,38.393 h2
  text "Top Layer - Bottom Layer" at 257.441,38.393 h2
  text "1" at 207.181,38.392 h2
  text "NPTH" at 237.19,38.392 h2
  text "Round" at 245.438,38.392 h2
  text "Pad" at 280.192,38.392 h2
  text "Rounded" at 290.029,38.392 h2
  text "-" at 302.876,38.392 h2
  text "1.700mm (66.93mil)" at 217.94,34.253 h2
  text "6" at 207.181,34.252 h2
  text "PTH" at 237.19,34.251 h2
  text "Round" at 245.438,34.252 h2
  text "Top Layer - Bottom Layer" at 257.441,34.252 h2
  text "Pad" at 280.192,34.252 h2
  text "Rounded" at 290.029,34.252 h2
  text "-" at 302.876,34.251 h2
  text "2" at 207.181,30.111 h2
  text "2.200mm (86.61mil)" at 217.94,30.112 h2
  text "PTH" at 237.19,30.111 h2
  text "Round" at 245.438,30.111 h2
  text "Top Layer - Bottom Layer" at 257.441,30.112 h2
  text "Pad" at 280.192,30.111 h2
  text "Rounded" at 290.029,30.111 h2
  text "-" at 302.876,30.111 h2
  text "G" at 197.001,29.857 h1.84
  text "4" at 207.181,25.97 h2
  text "2.330mm (91.73mil)" at 217.94,25.971 h2
  text "PTH" at 237.19,25.97 h2
  text "Round" at 245.438,25.971 h2
  text "Top Layer - Bottom Layer" at 257.441,25.971 h2
  text "Pad" at 280.192,25.971 h2
  text "Rounded" at 290.029,25.971 h2
  text "-" at 302.876,25.97 h2
  text "6" at 207.181,21.83 h2
  text "3.200mm (125.98mil)" at 217.94,21.831 h2
  text "NPTH" at 237.19,21.83 h2
  text "Round" at 245.438,21.83 h2
  text "Top Layer - Bottom Layer" at 257.441,21.831 h2
  text "Pad" at 280.192,21.83 h2
  text "Rounded" at 290.029,21.83 h2
  text "-" at 302.876,21.829 h2
  text "4" at 207.181,17.689 h2
  text "3.300mm (129.92mil)" at 217.94,17.69 h2
  text "PTH" at 237.19,17.689 h2
  text "Round" at 245.438,17.689 h2
  text "Top Layer - Bottom Layer" at 257.441,17.69 h2
  text "Pad" at 280.192,17.689 h2
  text "Rounded" at 290.029,17.689 h2
  text "-" at 302.876,17.689 h2
  text "2" at 207.181,13.548 h2
  text "3.400mm (133.86mil)" at 217.94,13.55 h2
  text "PTH" at 237.19,13.548 h2
  text "Round" at 245.438,13.549 h2
  text "Top Layer - Bottom Layer" at 257.441,13.549 h2
  text "Pad" at 280.192,13.549 h2
  text "Rectangle" at 290.029,13.549 h2
  text "-" at 302.876,13.548 h2
  text "J" at 197.001,13.295 h1.84
  text "5" at 207.181,9.408 h2
  text "3.500mm (137.79mil)" at 217.94,9.409 h2
  text "PTH" at 237.19,9.408 h2
  text "Round" at 245.438,9.408 h2
  text "Top Layer - Bottom Layer" at 257.441,9.409 h2
  text "Pad" at 280.192,9.408 h2
  text "Rounded" at 290.029,9.408 h2
  text "-" at 302.876,9.408 h2
  text "C" at 197.001,9.154 h1.84
  text "2429 Total" at 207.181,5.268 h2
  text "Slot definitions :" at 197.789,2.369 h2
  text "Routed Path Length" at 211.423,2.37 h2
  text "= Calculated from tool start centre position to tool end centre position." at 228.312,2.369 h2
  text "Hole Length" at 211.423,0.713 h2
  text "= Routed Path Length + Tool Size = Slot length as defined in the PCB layout" at 222.044,0.713 h2

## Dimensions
85.5,123.578 to 88.1,126.178 on M3-Top Dimensions
62.5,123.578 to 85.5,123.578 on M3-Top Dimensions
5,132 to 62.5,123.578 on M3-Top Dimensions
5,132 to 0.893,127.893 on M3-Top Dimensions
172,1 to 167,5 on M3-Top Dimensions
0,1 to 5,5 on M3-Top Dimensions
95.954,141.025 to 166.725,117.4 on M3-Top Dimensions
5,141.525 to 95.954,132.163 on M3-Top Dimensions
0,136 to 5,132 on M3-Top Dimensions
167.995,64.27 to 175.7,57 on M3-Top Dimensions
167,57 to 166.725,117.4 on M3-Top Dimensions
176.75,32.8 to 167,57 on M3-Top Dimensions
176.75,5 to 167,32.8 on M3-Top Dimensions
171,0 to 167,5 on M3-Top Dimensions
0,136 to 172,136 on M3-Top Dimensions
1,0 to 1,137 on M3-Top Dimensions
